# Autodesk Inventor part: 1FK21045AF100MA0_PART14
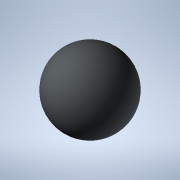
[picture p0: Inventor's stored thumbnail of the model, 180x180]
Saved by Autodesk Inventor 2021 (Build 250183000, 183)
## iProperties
Created: 2025-04
Part Number: 1FK21045AF100MA0_PART14
Material: Generic
Catalog Web Link: www.3dfindit.com
Description: -Servo synchronous motor
Document SubType Name: Modeling
Designer: psAdmin
Mass: 0.137258 g
Surface Area: 1.2868 cm^2
Volume: 0.137258 cm^3
Density: 1 g/cm^3
Appearance: PSOLRGB-212-217-219
Category: PARTsolutions
Title: 1FK21045AF100MA0_PART14
Author: Cadenas PARTsolutions
Comments: Servo synchronous motor
Sending System: PARTsolutions
Preprocessor: ST-DEVELOPER v19.3
PSOL_IDENT_0: {$CADENAS_DATA/23d-libs/siemens_ag/_cat_/52/6b/1fk21045af100ma0.prj},216 {VTYP=3D},{NB=1FK21045AF100
PSOL_IDENT_1: MA0_PART14},{LINA=1FK21045AF100MA0_PART14},{NN=1FK21045AF100MA0_PART14},{NOPRJ=TRUE},{DATE=19.08.202
PSOL_IDENT_2: 5 14:00:38},{GEOMDATE=30.07.2025 02:01:45},{VERSION=},{LINEID=10},{WBVAR=},{WBNUMERIC=}  {NB=1FK2104
PSOL_IDENT_3: 5AF100MA0_PART14},{LINA=1FK21045AF100MA0_PART14},{KT=DUMMY},{PREVIEW=../../../_pool_/cb/72/p_d211_xx
PSOL_IDENT_4: _00434j.png},{DESCSHORT=SIMOTICS S-1FK2 HD, SINAMICS S210 3AC 400V-480V, 2.4 Nm, 3000 rpm},{DESCLONG=
PSOL_IDENT_5: SIMOTICS S-1FK2 HD servo motor M0=2.4 Nm; PN = 0.75 kW at nN=3000 rpm (380-480 V); PN = 0.375 kW at
PSOL_IDENT_6: nN=1500 rpm (200-240 V); with holding brake; degree of protection IP64; cylindrical shaft D19x40mm;
PSOL_IDENT_7: absolute encoder 22-bit + 12-bit multiturn (encoder AM22DQC); with OCC interface; plug size M17, rot
PSOL_IDENT_8: atable; SIMOTICS S-1FK2 servomotorfor a wide range of uses in industrial environments. SIMOTICS S‑1F
PSOL_IDENT_9: K2 servomotors are compact synchronous motors with a high dynamic performance that set themselves ap
PSOL_IDENT_10: art as a result of their high power density, degree of protection and overload capability. The motor
PSOL_IDENT_11: s are available in two variants: as High Dynamic variant (highest dynamic performance as a result of
PSOL_IDENT_12: the low intrinsic moment of inertia for applications demanding a high dynamic performance with low
PSOL_IDENT_13: moved masses) - and as Compact variant (precise and stable closed-loop control for medium up to larg
PSOL_IDENT_14: e moved masses as a result of a medium intrinsic moment of inertia). SIMOTICSS‑1FK2 servomotors full
PSOL_IDENT_15: y exploit their strengths in a system with the SINAMICSS210 frequency converter and simple connectio
PSOL_IDENT_16: n using the one cable connection (OCC). Advantages include the short control and positioning times,
PSOL_IDENT_17: fast and precise correction of disturbing quantities as well as stable control with a high dynamic p
PSOL_IDENT_18: erformance. The servo motors can be configured to address a wide range of requirements. For example
PSOL_IDENT_19: with and without holding brake, IP64 or IP65 degree of protection, singleturn or multiturn absolute
PSOL_IDENT_20: encoders - to name just a few. Further, the servomotors are available in different shaft heights ext
PSOL_IDENT_21: ending from 20 to 100. A shaft sealing ring is available to achieve an IP65 degree of protection and
PSOL_IDENT_22: for subsequent mounting at the motor or as spare part. SIMOTICS - the optimum motor for each and ev
PSOL_IDENT_23: ery motion control application.},{INTNO=804766906411},{SUPPLIERALTNO=1FK2104-5AF10-0MA0},{MANUID=1FK
PSOL_IDENT_24: 21045AF100MA0},{MANUNAME=Siemens},{MANUTYPEDESC=Synchronous motor 1FK2-HD 2.4 NM},{AAU732=SIMOTICS},
PSOL_IDENT_25: {AAO057=S-1FK2},{AAU734=SIMOTICS S-1FK2 HD servo motor M0=2.4 Nm; PN = 0.75 kW at nN=3000 rpm (380-4
PSOL_IDENT_26: 80 V); PN = 0.375 kW at nN=1500 rpm (200-240 V); with holding brake; degree of protection IP64; cyli
PSOL_IDENT_27: ndrical shaft D19x40mm; absolute encoder 22-bit + 12-bit multiturn (encoder AM22DQC); with OCC inter
PSOL_IDENT_28: face; plug size M17, rotatable;},{AAW338=Synchronous motor 1FK2-HD 2.4 NM},{AAO742=SIMOTICS},{AAO663=
PSOL_IDENT_29: 4042948693070},{NOCUPEROU=1},{PRICEQUANTITY=1},{QUANTITYMIN=1},{QUANTITYINT=1},{CTN=85015100},{COO=D
PSOL_IDENT_30: E},{AAO676=1FK2104-5AF10-0MA0},{AAO677=Siemens AG},{ORDERUNIT=C62},{CONTENTUNIT=C62}
NB: 1FK21045AF100MA0_PART14
NT: Servo synchronous motor
NBSYN: $MANUID._PART14
LINA: 1FK21045AF100MA0_PART14
CATALOG: SIEMENS
PREVIEW: ../../../_pool_/cb/72/p_d211_xx_00434j.png
DESCSHORT: SIMOTICS S-1FK2 HD, SINAMICS S210 3AC 400V-480V, 2.4 Nm, 3000 rpm
DESCLONG: SIMOTICS S-1FK2 HD servo motor M0=2.4 Nm; PN = 0.75 kW at nN=3000 rpm (380-480 V); PN = 0.375 kW at nN=1500 rpm (200-240 V); with holding brake; degree of prote
INTNO: 804766906411
SUPPLIERALTNO: 1FK2104-5AF10-0MA0
MANUID: 1FK21045AF100MA0
MANUNAME: Siemens
MANUTYPEDESC: Synchronous motor 1FK2-HD 2.4 NM
AAU732: SIMOTICS
AAO057: S-1FK2
AAU734: SIMOTICS S-1FK2 HD servo motor M0=2.4 Nm; PN = 0.75 kW at nN=3000 rpm (380-480 V); PN = 0.375 kW at nN=1500 rpm (200-240 V); with holding brake; degree of prote
AAW338: Synchronous motor 1FK2-HD 2.4 NM
AAO742: SIMOTICS
AAO663: 4042948693070.0
NOCUPEROU: 1
PRICEQUANTITY: 1
QUANTITYMIN: 1
QUANTITYINT: 1
CTN: 85015100
COO: DE
ARTICLENO: 1FK21045AF100MA0_PART14
BOMINFO: 1FK21045AF100MA0_PART14
CREATOR: CADENAS GmbH
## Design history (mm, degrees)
feature "2025_04_17_15_34_52_0317"
body "Solid1"
